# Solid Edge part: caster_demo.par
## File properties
Author: edge
Template: Jis Part.par
Last saved by: edge
Revision: 11
Application: Solid Edge
文書内容のタイプ: 0
Accuracy: 0.990
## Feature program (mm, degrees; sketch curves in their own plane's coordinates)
sketch for "unnamed Protrusion 1" #1 plane through (0, 0, 0) normal (0, -1, 0) x-axis (1, 0, 0)
  circle centre (-83.0719, 0) radius 50
sketch for "unnamed Protrusion 1" #2 plane through (0, 0, 0) normal (0, -1, 0) x-axis (1, 0, 0)
  line (50, -37.5) -> (-50, -37.5)
  line (-50, -37.5) -> (-50, 37.5)
  line (-50, 37.5) -> (50, 37.5)
  line (50, 37.5) -> (50, -37.5)
  dimension (linear) = 50
  dimension (linear) = 50
extrude "unnamed Protrusion 1" add finite 100 symmetric
sketch for "unnamed RevolvedCutout 1" plane through (0, 0, 0) normal (0, -1, 0) x-axis (1, 0, 0)
  arc centre (-57.4597, 0) radius 80 from (-5.0694, 60.4587) to (20, 20) cw
  line (20, 20) -> (30, 20)
  line (30, 20) -> (35.7735, 10)
  line (35.7735, 10) -> (50, 10)
  dimension (linear) = 20
revolve "unnamed RevolvedCutout 1" cut full turn 360 deg
sketch for "unnamed Cutout 1" plane through (0, 0, 0) normal (0, 0, 1) x-axis (1, 0, 0)
  line (-133.0719, 30) -> (-30, 30)
  line (-30, 30) -> (-30, -30)
  line (-30, -30) -> (-133.0719, -30)
  dimension (linear) = 133.0719
extrude "unnamed Cutout 1" cut through
sketch for "突き出し_2" plane through (-64.0408, -50, 0) normal (0, -1, 0) x-axis (1, 0, 0)
  circle centre (-19.0311, 0) radius 30
extrude "突き出し_2" add finite 20 along +normal
draft "Draft_2"  Angles1 = 20 deg
mirror "unnamed Mirror 1" of "突き出し_2"
pattern "unnamed Pattern 1"
sketch for "Hole_1" plane through (0, 0, 0) normal (0, -1, 0) x-axis (1, 0, 0)
hole "Hole_1" diameter 22 through
thinwall "Thinwall_1"  Thickness = 2 mm
web network "WebNetwork_1"  Profile_Plane1_Distance = 5 mm; Thickness = 2 mm
mirror "unnamed Mirror 2" of "WebNetwork_1" about plane through (0, 0, 0) normal (0, -1, 0)
web network "unnamed WebNetwork 1"
fillet "Round_1" radius 5
fillet "Round_2" radius 3
fillet "Round_3" radius 2
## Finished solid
Body 1: solid body, 83 faces, 194 edges, 112 vertices.
  Faces by surface: plane 49, cylinder 12, cone 10, torus 10, sphere 2
  Edges by curve: circle 82, line 80, intersection 32
Bounding box of the edges (mm; curved faces can reach further): 183.072 x 140.000 x 100.000, from (-133.0719, -70, -50) to (50, 70, 50).
Cylindrical faces by radius (mm): R8 x1, R10 x1, R11 x2, R13 x2, R18 x1, R20 x1, R48 x2, R50 x2
Conical faces (half-angle, radius in mm at the cone's reference point): 20 deg R28.1206 x2, 20 deg R30 x2, 40.9105 deg R58.9472 x4, 60 deg R19 x1, 60 deg R20 x1
Toroidal faces (ring radius, tube radius in mm): R18 r2 x1, R22 r2 x1, R27.8994 r3 x2, R39.38 r3 x2, R60 r5 x2, R67.5925 r5 x2
Spherical faces by radius (mm): R78 x1, R80 x1
Planar faces by outward normal: +x 5, +y 13, +z 6, -x 6, -y 13, -z 6
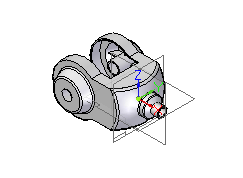
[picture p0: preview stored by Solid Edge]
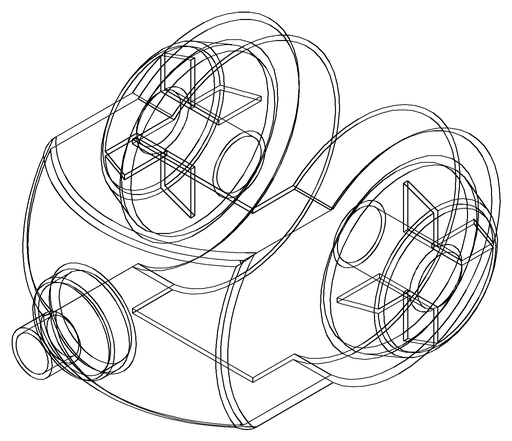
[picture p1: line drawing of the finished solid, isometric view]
